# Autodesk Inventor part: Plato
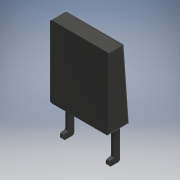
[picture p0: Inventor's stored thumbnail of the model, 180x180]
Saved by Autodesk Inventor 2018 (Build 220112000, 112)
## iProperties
Created: 2022-01
Part Number: Plato
Material: Plástico, negro opaco
Document SubType Name: Modeling
Designer: Asus
Density: 0.952 g/cm^3
Appearance: Suave - Negro
Author: Asus
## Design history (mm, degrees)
sketch "Boceto1"
  geometry: L1 (-110, 0.114)-(-110, 270.114); L2 (-110, 0.114)-(110, 0.114); L3 (110, 0.114)-(110, 270.114); L4 (110, 270.114)-(-110, 270.114); L5 (-110, 270.114)-(-110, 0.114); 1 further point
  constraints: 10 end point, 2 parallel, 1 horizontal, 1 perpendicular
  dimensions: "d2" = 110 distance of point (0, 0) L1.start; "d3" = 270 distance of L1.start L1.end; "d4" = 220 distance of L4.end L3.end; "d5" = 270 distance of L3.end L2.end
extrude "Extrusión1" new body sketch "Boceto1" distance "d6" = 80; taper "d7" = 0 deg
sketch "Boceto2"
  geometry: L1 (97.5, -257.5)-(-97.5, -257.5); L2 (-97.5, -257.5)-(-97.5, -12.5); L3 (-97.5, -12.5)-(97.5, -12.5); L4 (97.5, -12.5)-(97.5, -257.5); L5 (97.5, -257.5)-(-97.5, -12.5); L6 (-97.5, -257.5)-(97.5, -12.5); 2 further points
  constraints: 12 end point, 2 midpoint, 2 parallel, 1 horizontal, 1 perpendicular
  dimensions: "d8" = 195 distance of L2.end L3.end; "d9" = 245 distance of L1.end L2.end
extrude "Extrusión2" cut sketch "Boceto2" distance "d10" = 65; taper "d11" = 0 deg
sketch "Boceto3"
  geometry: L1 (0, 80)-(270, 80) reference; L2 (0, 80)-(0, 60); L3 (0, 0)-(0, 80) reference; L4 (270, 0)-(270, 80) reference; L5 (0, 60)-(270, 80); L6 (270, 80)-(0, 80); 1 further point
  constraints: 6 end point, 1 perpendicular, 1 point on line
  dimensions: "d12" = 20 distance of L1.start L2.end
extrude "Extrusión3" cut sketch "Boceto3" distance "d13" = 220; taper "d14" = 0 deg
fillet "Empalme1" dims "d15" = 7.5
sketch "Boceto4"
  geometry: L1 (22.5, 80)-(182.5, 80); L2 (182.5, 80)-(182.5, 30); L3 (182.5, 30)-(22.5, 30); L4 (22.5, 30)-(22.5, 80); L5 (22.5, 80)-(182.5, 30); L6 (182.5, 80)-(22.5, 30); 2 further points
  constraints: 12 end point, 2 midpoint, 2 parallel, 1 horizontal, 1 perpendicular
  dimensions: "d16" = 160 distance of L2.end L3.end; "d17" = 50 distance of L1.end L2.end
extrude "Extrusión4" cut sketch "Boceto4" distance "d18" = 50; taper "d19" = 0 deg
sketch "Boceto5"
  geometry: L1 (22.5, 60)-(10, 60); L2 (10, 60)-(10, 20); L3 (10, 20)-(22.5, 20); L4 (22.5, 20)-(22.5, 60); L5 (182.5, 60)-(195, 60); L6 (195, 60)-(195, 20); L7 (195, 20)-(182.5, 20); L8 (182.5, 20)-(182.5, 60); 3 further points
  constraints: 16 end point, 4 parallel, 2 horizontal, 2 perpendicular
  dimensions: "d20" = 40 distance of L2.end L1.end; "d21" = 40 distance of L5.end L6.end
extrude "Extrusión5" join sketch "Boceto5" distance "d22" = 120; taper "d23" = 0 deg
sketch "Boceto6"
  geometry: L1 (0, 0)-(120, 0) reference; L2 (0, 0)-(0, 20); L3 (0, -20)-(0, 60) reference; L4 (0, 20)-(100, 20); L5 (100, 20)-(100, 0); L6 (100, 0)-(0, 0); 1 further point
  constraints: 8 end point, 2 perpendicular, 1 vertical
  dimensions: "d24" = 20 distance of L1.start L2.end; "d26" = 100 distance of L2.end L4.end; "d27" = 20 distance of L4.end L5.end
extrude "Extrusión6" cut sketch "Boceto6" distance "d28" = 200; taper "d29" = 0 deg
fillet "Empalme2" dims "d30" = 7.5
node "Sólido1"
